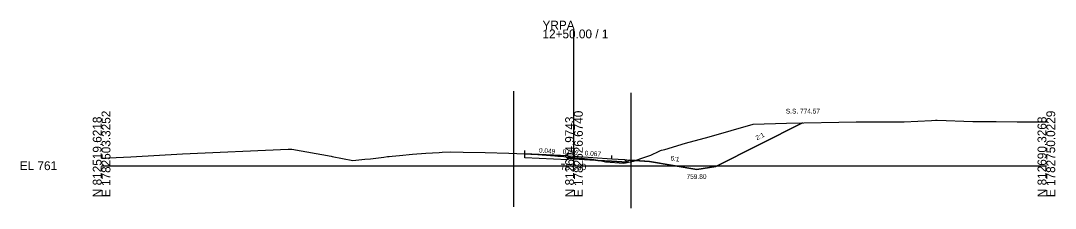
# Model space of a CAD drawing. Extents: x -26 to 2603, y -14 to 9545.
# Drawn here: x -25.7 to 302.8, y 2486.5 to 2546.1 of the extents above; entities that cross this region are included whole.
import ezdxf

# ---------------------------------------------------------------- set-up
doc = ezdxf.new("R2010")
doc.units = 0
for name, color, linetype in [('Exist Cross Section Cell', 7, 'Continuous'), ('Exist XS Center Line Elevation Label', 7, 'Continuous'), ('Exist XS Ground Line', 7, 'Continuous'), ('Prop XS Ditch Slope Text', 7, 'Continuous'), ('Prop XS Ditch Standard Text', 7, 'Continuous'), ('Prop XS Dump Level', 7, 'Continuous'), ('Prop XS Earthwork Shape', 7, 'Continuous'), ('Prop XS EOT Tick Mark', 7, 'Continuous'), ('Prop XS Exc Vertical Line 2', 7, 'Continuous'), ('Prop XS Finish Grade', 7, 'Continuous'), ('Prop XS Finish Grade Earthwork', 7, 'Continuous'), ('Prop XS Finish Grade Paved Shoulder', 7, 'Continuous'), ('Prop XS Finish Grade Pavement', 7, 'Continuous'), ('Prop XS Pvmt Edge Slope', 7, 'Continuous'), ('Prop XS SE Text', 7, 'Continuous'), ('Prop XS Side Slope Text', 7, 'Continuous'), ('Prop XS SS Elevation Text', 7, 'Continuous'), ('Prop XS Subgrade Earthwork', 7, 'Continuous'), ('Scratch_Level_6', 7, 'Continuous')]:
    doc.layers.add(name, color=color, linetype=linetype)

msp = doc.modelspace()

# ---------------------------------------------------------------- linework, layer by layer
at = {"layer": 'Exist Cross Section Cell'}
for p, q in [((150, 2500), (150, 2543.26)), ((0, 2500), (150, 2500)), ((150, 2500), (300, 2500))]:
    msp.add_line(p, q, dxfattribs=at)
at = {"layer": 'Exist XS Ground Line'}
for p, q in [((206.85, 2513.18), (217.5, 2513.46)), ((217.5, 2513.46), (239.6, 2513.96)), ((239.6, 2513.96), (254.8, 2513.97)), ((254.8, 2513.97), (263.48, 2514.37)), ((263.48, 2514.37), (264.79, 2514.42)), ((264.79, 2514.42), (265.3, 2514.42)), ((265.3, 2514.42), (276.63, 2514)), ((276.63, 2514), (282.31, 2514.04)), ((282.31, 2514.04), (283.11, 2514.08)), ((283.11, 2514.08), (284.1, 2514.04)), ((284.1, 2514.04), (290.77, 2513.96)), ((290.77, 2513.96), (297.3, 2513.9)), ((297.3, 2513.9), (300, 2513.9)), ((192.96, 2509.14), (206.85, 2513.18)), ((178.89, 2505.2), (185.45, 2507.11)), ((185.45, 2507.11), (192.96, 2509.14)), ((9.27, 2502.87), (25.73, 2503.75)), ((25.73, 2503.75), (59.26, 2505.3)), ((59.26, 2505.3), (60.37, 2505.3)), ((60.37, 2505.3), (72.9, 2503.03)), ((94.61, 2503.29), (98.68, 2503.7)), ((98.68, 2503.7), (102.93, 2503.96)), ((102.93, 2503.96), (107.19, 2504.24)), ((107.19, 2504.24), (108.16, 2504.29)), ((108.16, 2504.29), (110.66, 2504.39)), ((110.66, 2504.39), (114.76, 2504.3)), ((114.76, 2504.3), (121.75, 2504.17)), ((121.75, 2504.17), (129.32, 2503.95)), ((129.32, 2503.95), (134.44, 2503.8)), ((134.44, 2503.8), (136.32, 2503.68)), ((136.32, 2503.68), (138.55, 2503.54)), ((138.55, 2503.54), (143.91, 2503.15)), ((174.42, 2503.37), (177.03, 2504.67)), ((177.03, 2504.67), (177.48, 2504.8)), ((177.48, 2504.8), (177.81, 2504.93)), ((177.81, 2504.93), (178.89, 2505.2)), ((0, 2502.37), (9.27, 2502.87)), ((72.9, 2503.03), (73.23, 2502.97)), ((73.23, 2502.97), (79.77, 2501.63)), ((79.77, 2501.63), (83.58, 2502.03)), ((83.58, 2502.03), (85.41, 2502.23)), ((85.41, 2502.23), (89.64, 2502.75)), ((89.64, 2502.75), (90.81, 2502.89)), ((90.81, 2502.89), (91.36, 2502.97)), ((91.36, 2502.97), (92.28, 2503.06)), ((92.28, 2503.06), (94.61, 2503.29)), ((143.91, 2503.15), (144.87, 2503.08)), ((144.87, 2503.08), (145.3, 2503.07)), ((145.3, 2503.07), (145.74, 2503)), ((145.74, 2503), (150, 2502.6)), ((150, 2502.6), (152.34, 2502.38)), ((152.34, 2502.38), (155.27, 2502.1)), ((155.27, 2502.1), (155.69, 2502.03)), ((155.69, 2502.03), (158.77, 2501.5)), ((158.77, 2501.5), (159.98, 2501.24)), ((159.98, 2501.24), (165.82, 2500.78)), ((165.82, 2500.78), (168.85, 2501.46)), ((168.85, 2501.46), (169.21, 2501.58)), ((169.21, 2501.58), (171.89, 2502.46)), ((171.89, 2502.46), (174.42, 2503.37))]:
    msp.add_line(p, q, dxfattribs=at)
at = {"layer": 'Prop XS Dump Level'}
for p, q in [((148, 2503.14), (150, 2503)), ((150, 2503), (162, 2502.2))]:
    msp.add_line(p, q, dxfattribs=at)
at = {"layer": 'Prop XS Earthwork Shape'}
for points in [[(169.46, 2501.66), (171.89, 2502.46), (174.42, 2503.37), (177.03, 2504.67), (177.48, 2504.8), (177.81, 2504.93), (178.89, 2505.2), (185.45, 2507.11), (192.96, 2509.14), (206.85, 2513.18), (217.5, 2513.46), (222.55, 2513.57), (195, 2499.8), (189, 2498.8), (174, 2501.3)], [(155.69, 2502.03), (157.59, 2501.7), (149.95, 2502.21), (148, 2502.34), (148, 2501.89), (134.43, 2502.55), (134.43, 2503.8), (136.32, 2503.68), (138.55, 2503.54), (143.91, 2503.15), (144.87, 2503.08), (145.3, 2503.07), (145.74, 2503), (150, 2502.6), (152.34, 2502.38), (155.27, 2502.1)], [(169.21, 2501.58), (169.46, 2501.66), (167.57, 2501.81), (166.85, 2501.09), (161.95, 2501.41), (157.59, 2501.7), (158.77, 2501.5), (159.98, 2501.24), (165.82, 2500.78), (168.85, 2501.46)]]:
    msp.add_lwpolyline(points, close=True, dxfattribs=at)
at = {"layer": 'Prop XS EOT Tick Mark'}
for p, q in [((134.43, 2503.8), (134.43, 2504.8)), ((148, 2503.14), (148, 2504.14)), ((162, 2502.2), (162, 2503.2))]:
    msp.add_line(p, q, dxfattribs=at)
at = {"layer": 'Prop XS Exc Vertical Line 2'}
for p, q in [((130.89, 2486.95), (130.89, 2523.63)), ((168.19, 2486.47), (168.19, 2523.15))]:
    msp.add_line(p, q, dxfattribs=at)
at = {"layer": 'Prop XS Finish Grade'}
msp.add_line((166, 2501.94), (167.57, 2501.81), dxfattribs=at)
at = {"layer": 'Prop XS Finish Grade Earthwork'}
for p, q in [((195, 2499.8), (222.55, 2513.57)), ((167.57, 2501.81), (174, 2501.3)), ((174, 2501.3), (189, 2498.8)), ((189, 2498.8), (195, 2499.8))]:
    msp.add_line(p, q, dxfattribs=at)
at = {"layer": 'Prop XS Finish Grade Paved Shoulder'}
for p, q in [((148, 2503.14), (134.43, 2503.8)), ((162, 2502.2), (166, 2501.94))]:
    msp.add_line(p, q, dxfattribs=at)
at = {"layer": 'Prop XS Finish Grade Pavement'}
for p, q in [((148, 2503.14), (150, 2503)), ((150, 2503), (162, 2502.2))]:
    msp.add_line(p, q, dxfattribs=at)
at = {"layer": 'Prop XS Pvmt Edge Slope'}
msp.add_line((166, 2501.94), (166.85, 2501.09), dxfattribs=at)
at = {"layer": 'Prop XS Subgrade Earthwork'}
for p, q in [((134.43, 2502.55), (134.43, 2503.8)), ((148, 2501.89), (134.43, 2502.55)), ((148, 2502.34), (149.95, 2502.21)), ((148, 2501.89), (148, 2502.34)), ((149.95, 2502.21), (161.95, 2501.41)), ((161.95, 2501.41), (166.85, 2501.09)), ((166.85, 2501.09), (167.57, 2501.81))]:
    msp.add_line(p, q, dxfattribs=at)
at = {"layer": 'Scratch_Level_6'}
msp.add_lwpolyline([(155.69, 2502.03), (157.59, 2501.7), (149.95, 2502.21), (148, 2502.34), (148, 2501.89), (134.43, 2502.55), (134.43, 2503.8), (136.32, 2503.68), (138.55, 2503.54), (143.91, 2503.15), (144.87, 2503.08), (145.3, 2503.07), (145.74, 2503), (150, 2502.6), (152.34, 2502.38), (155.27, 2502.1)], close=True, dxfattribs=at)

# ---------------------------------------------------------------- texts
at = {"layer": 'Exist Cross Section Cell'}
for s, p in [('YRPA', (140, 2543.26)), ('12+50.00 / 1', (140, 2540.46)), ('EL 761', (-26, 2498.6))]:
    msp.add_text(s, height=2.8, dxfattribs=at).set_placement(p)
for s, p in [('E 1782503.3252', (2.8, 2490)), ('E 1782626.6740', (152.8, 2490)), ('E 1782750.0229', (302.8, 2490)), ('N 812519.6218', (0, 2490)), ('N 812604.9743', (150, 2490)), ('N 812690.3268', (300, 2490))]:
    msp.add_text(s, height=2.8, rotation=90, dxfattribs=at).set_placement(p)
at = {"layer": 'Exist XS Center Line Elevation Label'}
msp.add_text('763.60', height=2, dxfattribs=at).set_placement((145.71, 2498.6))
at = {"layer": 'Prop XS Ditch Slope Text'}
msp.add_text('6:1', height=1.5, rotation=350.5377, dxfattribs=at).set_placement((180.55, 2501.73))
at = {"layer": 'Prop XS Ditch Standard Text'}
msp.add_text('759.80', height=1.5, dxfattribs=at).set_placement((185.74, 2495.8))
at = {"layer": 'Prop XS Dump Level'}
msp.add_text('Case4', height=0.04, dxfattribs=at).set_placement((174, 2501.26))
at = {"layer": 'Prop XS SE Text'}
for s, rotation, p in [('0.049', 355.4261, (138.82, 2504.2)), ('0.067', 356.1874, (146.37, 2503.74)), ('0.067', 356.1874, (153.37, 2503.28))]:
    msp.add_text(s, height=1.5, rotation=rotation, dxfattribs=at).set_placement(p)
at = {"layer": 'Prop XS Side Slope Text'}
msp.add_text('2:1', height=1.5, rotation=26.5651, dxfattribs=at).set_placement((208.1, 2508.03))
at = {"layer": 'Prop XS SS Elevation Text'}
msp.add_text('S.S. 774.57', height=1.5, dxfattribs=at).set_placement((217.28, 2516.57))

doc.saveas('drawing.dxf')
